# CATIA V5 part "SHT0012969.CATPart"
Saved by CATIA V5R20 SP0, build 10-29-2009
Part number: SHT0012969
Bounding box of the stored display mesh (mm): x 87.772 to 118.529, y -996.401 to -849.286, z 939.253 to 1127.424
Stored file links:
  D:\新建文件夹\宋国明\项目\02-福田A6-张甲\骨架钣金\2D\SHT0012969-安全带上悬置固定板\SHT0012969.CATPart
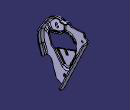
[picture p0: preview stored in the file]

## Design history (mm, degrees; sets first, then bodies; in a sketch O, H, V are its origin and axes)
Set1
  Point1: type Center, Curve edge [face of Solid1 | face of Solid1]
Body1 (main body)
Body2
  Solid1: solid without history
